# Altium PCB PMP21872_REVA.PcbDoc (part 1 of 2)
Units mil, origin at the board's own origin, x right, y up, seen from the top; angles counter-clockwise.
Board outline 2225 x 1350 mil, 4 copper layers (Top Layer, Signal Layer 1, Signal Layer 2, Bottom Layer), stack 61.6 mil thick; 75 components, 39 nets, 233 pads, 165 vias.
Unrouted connection lines stored in the file: 51.
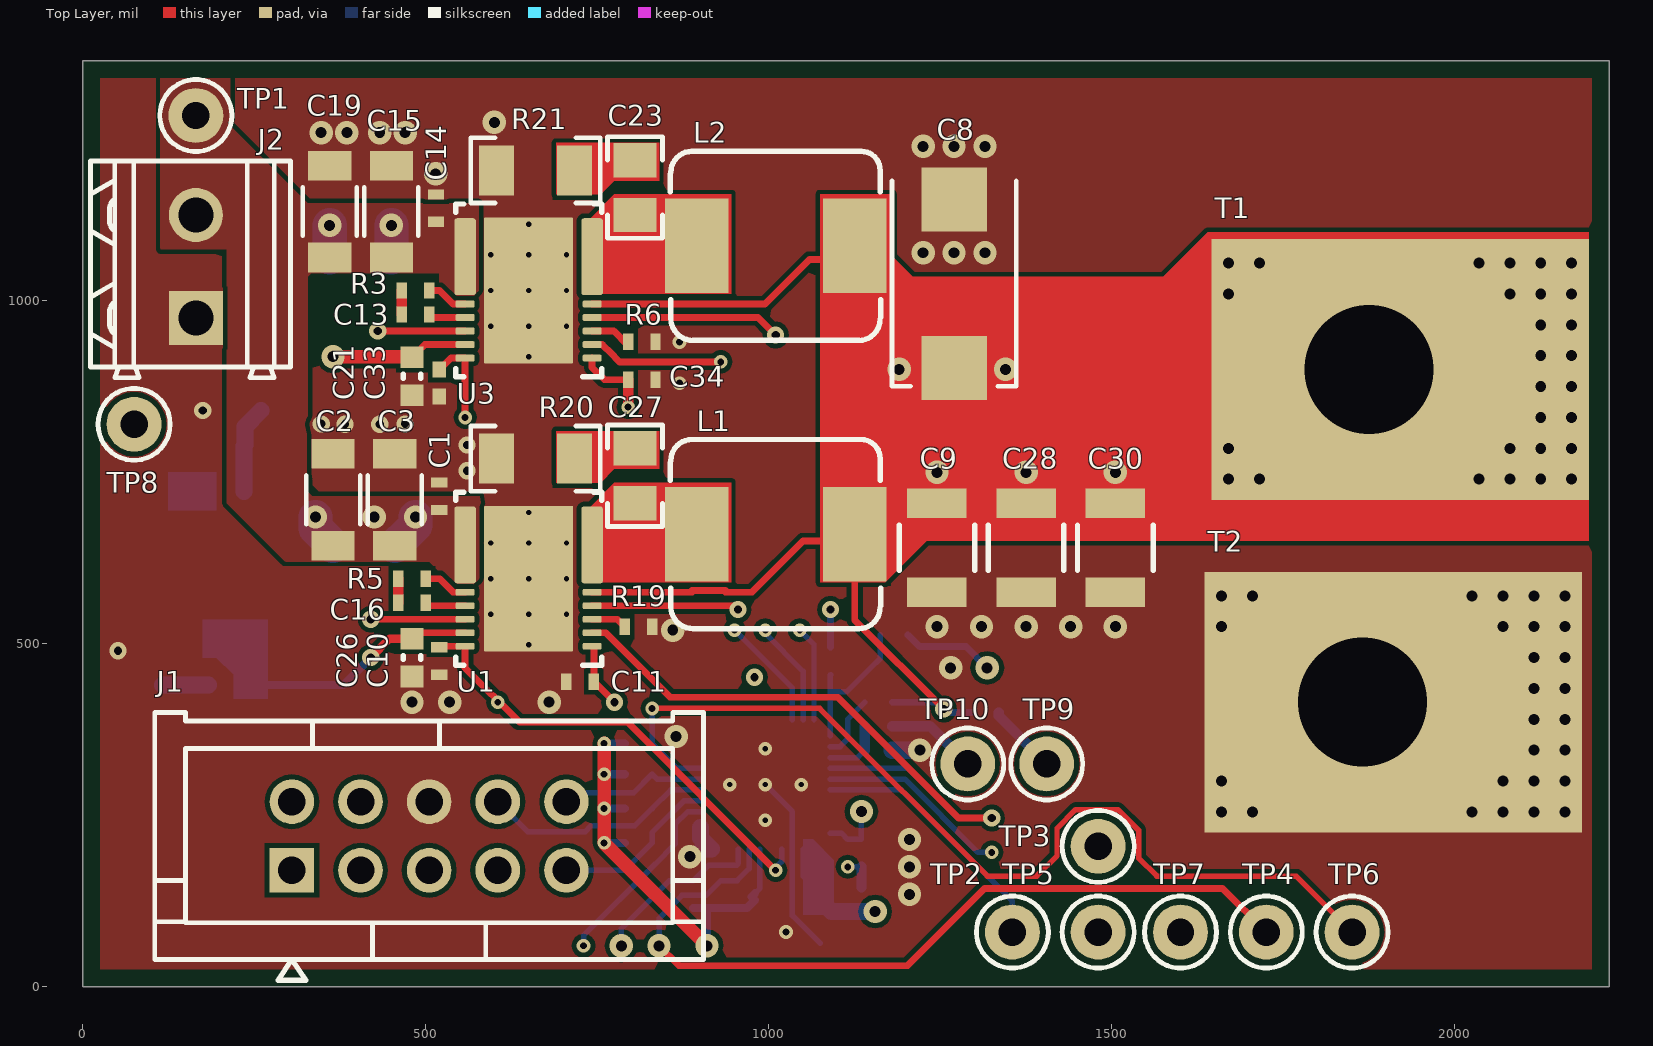
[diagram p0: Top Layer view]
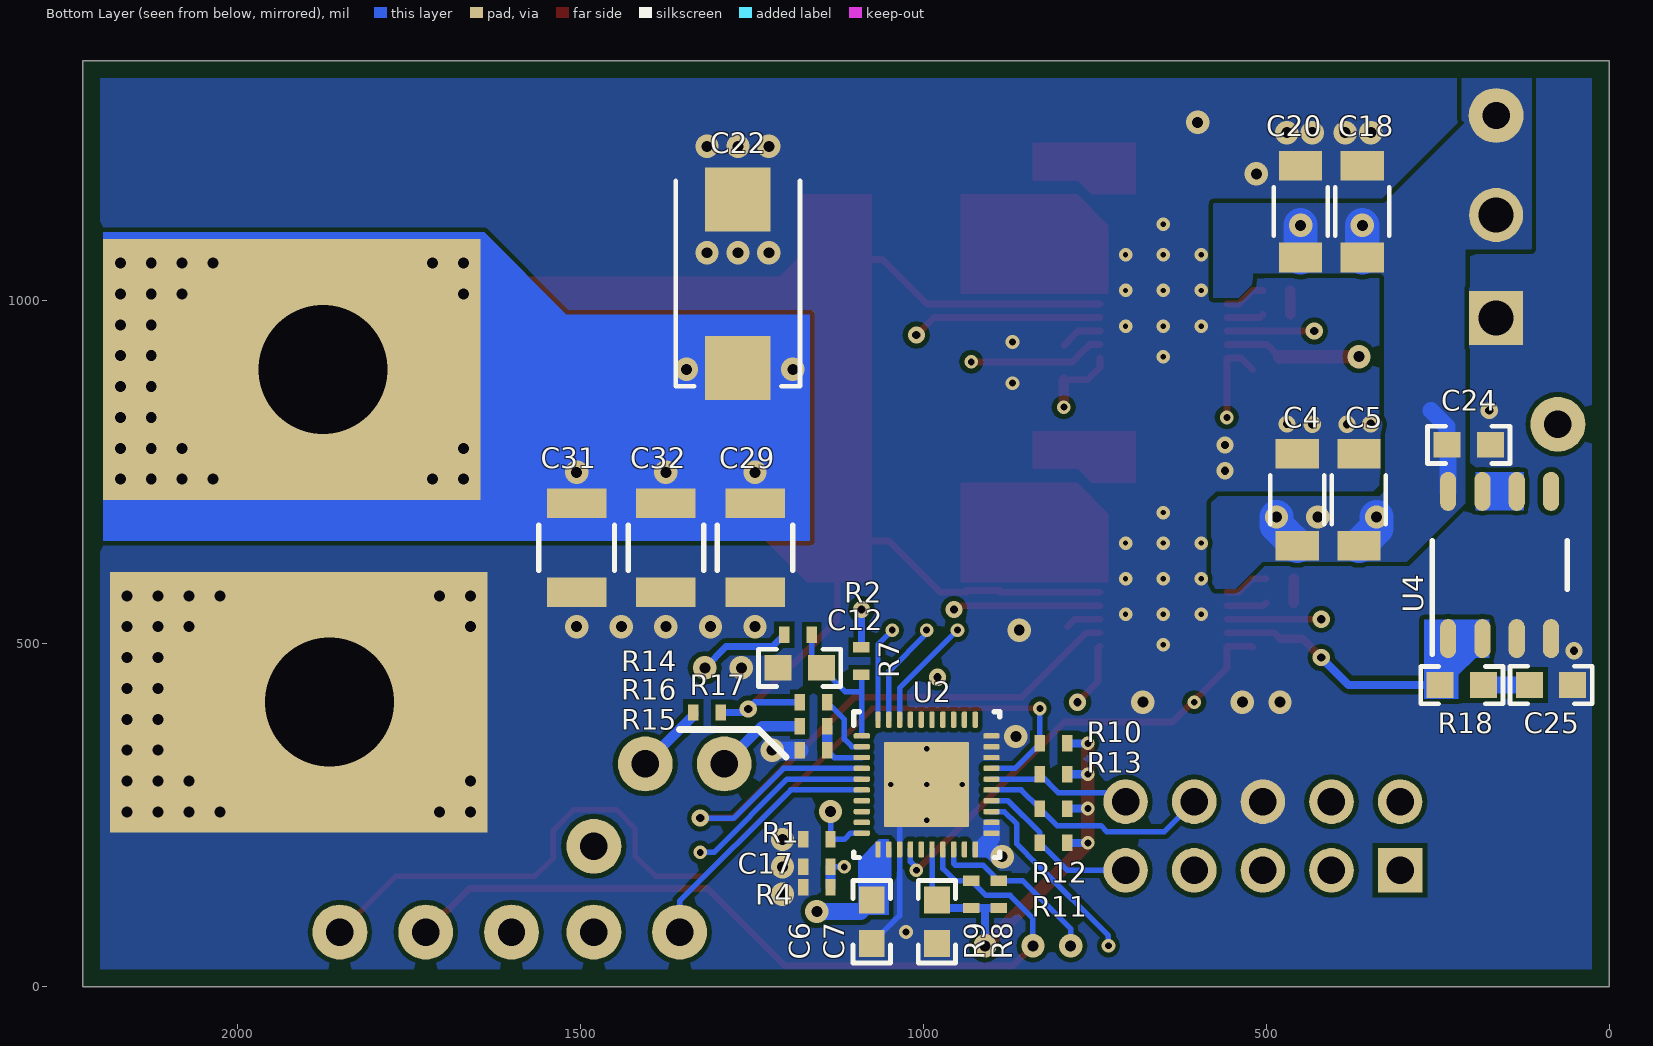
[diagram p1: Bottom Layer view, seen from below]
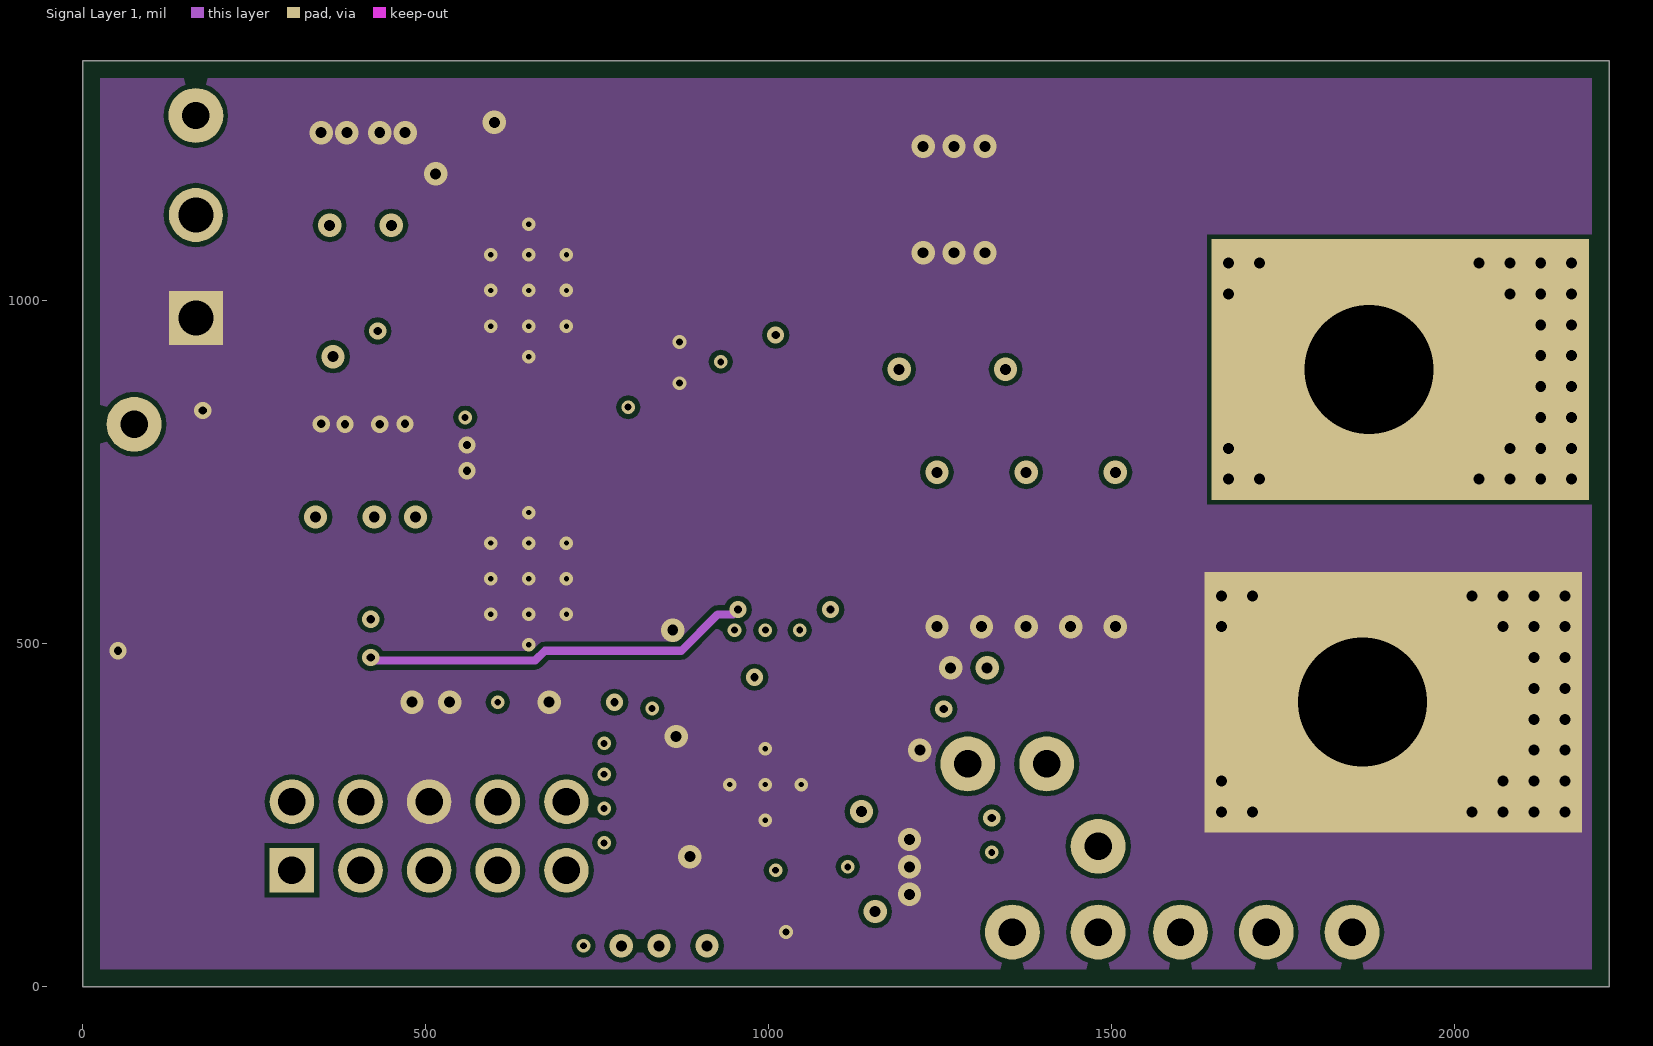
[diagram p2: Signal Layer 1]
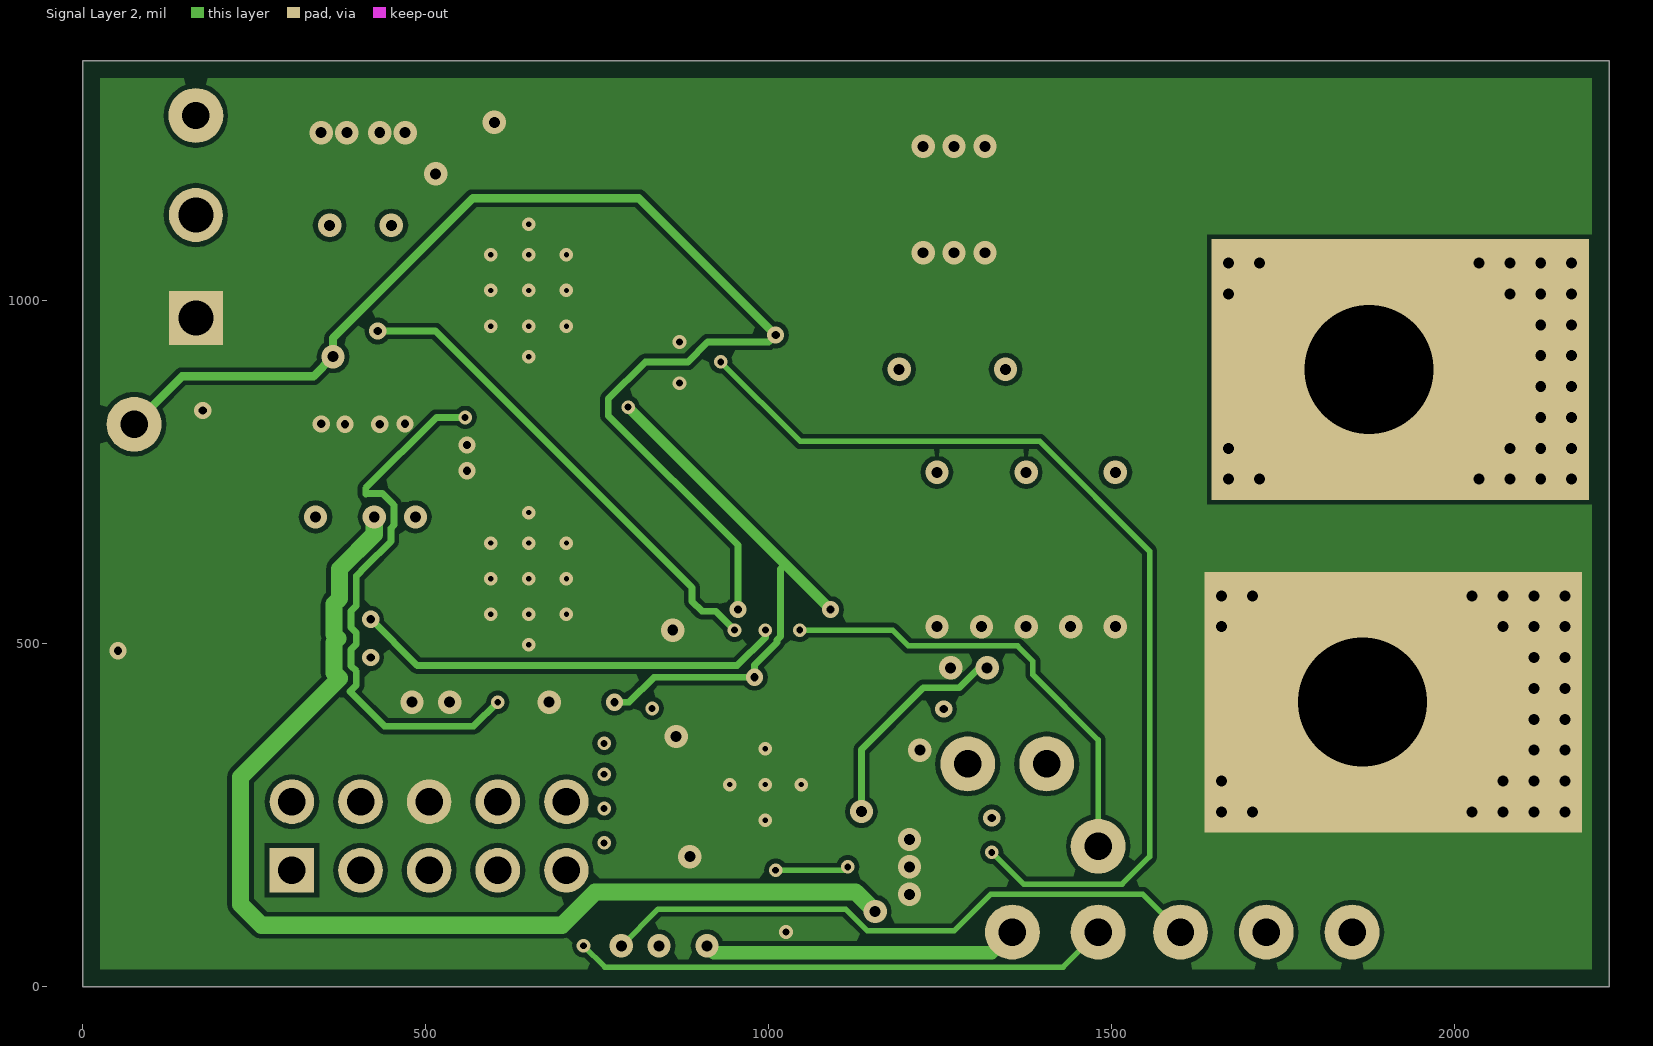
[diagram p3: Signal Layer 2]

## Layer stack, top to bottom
Top Solder: solder mask 0.4, Solder Resist, Dk 3.5
Top Layer: signal copper 1.4
Dielectric 1: prepreg 8, FR-4, Dk 4.2
Signal Layer 1: signal copper 1.4
Dielectric 2: core 40, FR-4, Dk 4.2
Signal Layer 2: signal copper 1.4
Dielectric 3: prepreg 8, FR-4, Dk 4.2
Bottom Layer: signal copper 1.4
Bottom Solder: solder mask 0.4, Solder Resist, Dk 3.5

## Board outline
0,0 2225,0 2225,1350 0,1350

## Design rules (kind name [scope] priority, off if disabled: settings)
AcuteAngle [All] p1: minimum=4.50000000000000E+0001 checktracksonly=FALSE
AssemblyTestPointUsage [All] p1: valid=2
BoardOutlineClearance BoardOutlineClearance_MountingHoles [OnCopper and InComponentClass('Mounting Holes')] p1: gap=25 ignorepadtopadclearanceinfootprint=FALSE
BoardOutlineClearance BoardOutlineClearance_Poly [OnCopper and InPoly] p2: gap=25 ignorepadtopadclearanceinfootprint=FALSE
BoardOutlineClearance [OnCopper and Not InComponentClass('Logo') and not InComponentClass('FiducialMark') and not InRegion(1000,500,4000,800)] p3: gap=25 ignorepadtopadclearanceinfootprint=FALSE
Clearance "Stitching to Stitching" [IsStitchingVia vs IsStitchingVia] p1: gap=7 ignorepadtopadclearanceinfootprint=FALSE
Clearance Clearance_Fiducial [InComponent('FID1') Or InComponent('FID2') Or InComponent('FID3')] p2: gap=0 ignorepadtopadclearanceinfootprint=FALSE
Clearance Clearance_Keepouts [((IsTrack Or IsArc) And Not InPoly) And IsFree and IsKeepOut vs ((IsTrack Or IsArc) And Not InPoly) And IsFree and IsKeepOut] p3: gap=0 ignorepadtopadclearanceinfootprint=FALSE
Clearance [All] p4: gap=7 ignorepadtopadclearanceinfootprint=FALSE
Clearance Clearance_Poly [InPolygon] p5: gap=4 ignorepadtopadclearanceinfootprint=FALSE
ComponentClearance ComponentClearance_BGA [HasParameterValue('CompType', 'IC')] p1: gap=4 collisioncheckmode=3 verticalgap=10 showdistances=TRUE
ComponentClearance ComponentClearance_Cap-Resistor [HasParameterValue('CompType', 'Resistor') Or HasParameterValue('CompType', 'Capacitor') Or HasParameterValue('CompType', 'Inductor')] p2: gap=4 collisioncheckmode=3 verticalgap=0 showdistances=TRUE
ComponentClearance ComponentClearance_MountingHoles_FiducialMarks [InComponentClass('Mounting Holes') vs InComponentClass('FiducialMark')] p3: gap=50 collisioncheckmode=3 verticalgap=10 showdistances=FALSE
ComponentClearance ComponentClearance_Shunt [InComponentClass('Header') vs InComponentClass('Shunt')] p4: gap=0 collisioncheckmode=3 verticalgap=0 showdistances=FALSE
ComponentClearance ComponentClearance_Logo [InComponentClass('Logo')] p5: gap=50 collisioncheckmode=3 verticalgap=10 showdistances=FALSE
ComponentClearance ComponentClearance_ScrewToNut [(HasFootprint('NY PMS 440 0025 PH')) vs (HasFootprint('Keystone_1902C'))] p6: gap=5 collisioncheckmode=3 verticalgap=10 showdistances=FALSE
ComponentClearance ComponentClearance_MountingHoles [InComponentClass('Mounting Holes')] p7: gap=250 collisioncheckmode=3 verticalgap=100000 showdistances=FALSE
ComponentClearance ComponentClearance_SmallPassives [HasFootprint('0201*') or HasFootprint('0402*') or HasFootprint('0508') or HasFootprint('0603*') or HasFootprint('0612') or HasFootprint('0805*') or HasFootprint('0815*') or HasFootprint('0830*') or HasFootprint('1206*') or HasFootprint('1210*') or HasFootprint('1808*') or HasFootprint('1812*') or HasFootprint('1825*') or HasFootprint('2010*') or HasFootprint('2220*') or HasFootprint('2225*') or HasFootprint('2512*') or HasFootprint('2728*') or HasFootprint('3518*') vs HasFootprint('0201*') or HasFootprint('0402*') or HasFootprint('0508') or HasFootprint('0603*') or HasFootprint('0612') or HasFootprint('0805*') or HasFootprint('0815*') or HasFootprint('0830*') or HasFootprint('1206*') or HasFootprint('1210*') or HasFootprint('1808*') or HasFootprint('1812*') or HasFootprint('1825*') or HasFootprint('2010*') or HasFootprint('2220*') or HasFootprint('2225*') or HasFootprint('2512*') or HasFootprint('2728*') or HasFootprint('3518*')] p8: gap=2 collisioncheckmode=3 verticalgap=10 showdistances=FALSE
ComponentClearance ComponentClearance_THtoSMT [IsThruComponent vs IsSMTComponent] p9: gap=15 collisioncheckmode=3 verticalgap=30 showdistances=FALSE
ComponentClearance ComponentClearance_THtoTH [IsThruComponent vs IsThruComponent] p10: gap=15 collisioncheckmode=3 verticalgap=30 showdistances=FALSE
ComponentClearance [All] p11: gap=2 collisioncheckmode=3 verticalgap=10 showdistances=FALSE
DiffPairsRouting [All] p1: maxlimit=100 minlimit=10 mostfreqgap=10 toplayer_minwidth=15 toplayer_maxwidth=15 toplayer_prefwidth=15 midlayer1_minwidth=15 midlayer1_maxwidth=15 midlayer1_prefwidth=15 midlayer2_minwidth=15 midlayer2_maxwidth=15 midlayer2_prefwidth=15 bottomlayer_minwidth=15 bottomlayer_maxwidth=15 bottomlayer_prefwidth=15 maxuncoupledlength=1000
FabricationTestPointUsage TestPointUsage [All] p1: valid=2 allowmultiple=FALSE
FabricationTestpoint Testpoint [All] p1: side=3 testpointundercomponent=TRUE minsize=40 maxsize=100 preferedsize=60 minholesize=0 maxholesize=40 preferedholesize=32 testpointgrid=1 allowsidetop=TRUE allowsidebottom=TRUE usegrid=TRUE gridtolerance=0.01
FanoutControl Fanout_LCC [IsLCC] p1: bgadir=Out bgaviamode=Centered fanoutstyle=Auto fanoutdirection=Alternating viagrid=1 // Fanout_LCC (Default Rule)
FanoutControl Fanout_BGA [IsBGA] p2: bgadir=Out bgaviamode=Centered fanoutstyle=Auto fanoutdirection=Alternating viagrid=1 // Fanout_BGA (Default Rule)
FanoutControl Fanout_Default [All] p4: bgadir=Out bgaviamode=Centered fanoutstyle=Auto fanoutdirection=Alternating viagrid=1 // Fanout_Default (Default Rule)
FanoutControl Fanout_Small [(CompPinCount < 5)] p5: bgadir=Out bgaviamode=Centered fanoutstyle=Auto fanoutdirection=OutThenIn viagrid=1 // Fanout_Small (Default Rule)
HoleSize [All] p1: absolutevalues=TRUE maxlimit=251 minlimit=5 maxpercent=80.000 minpercent=20.000
HoleToHoleClearance [All] p1: gap=6 allowstackedmicrovias=TRUE
MinimumAnnularRing MinimumAnnularRing_ThermalPadVias [IsVia and InAnyComponent] p1: minimumring=5.91
MinimumAnnularRing [All] p2: minimumring=1.5
MinimumSolderMaskSliver MinimumSolderMaskSliver_Logo [InComponentClass('Logo') vs InComponentClass('Logo')] p1: minsoldermaskwidth=0.7
MinimumSolderMaskSliver [All] p2: minsoldermaskwidth=1.5
PlaneClearance PlaneClearance_GND [InNet('GND')] p1: clearance=6
PlaneClearance PlaneClearance_GND_1 [InNet('GND') And InPolygon] p2: clearance=6
PlaneClearance [All] p3: clearance=15
PlaneConnect [All] p1: planeconnectstyle=Direct reliefexpansion=10 reliefentries=4 reliefconductorwidth=10 reliefairgap=10
PolygonConnect [All] p1: connectstyle=Direct reliefconductorwidth=10 reliefentries=4 polygonreliefangle="90 Angle" airgapwidth=10
RoutingVias RoutingVias_Connectors [HasCompParameterValue('PartNumber','CB35-36-CY')] p1: holewidth=12 width=32 viastyle="Through Hole" minholewidth=0 minwidth=0 maxholewidth=1000 maxwidth=1000
RoutingVias ThermalPadVias [IsVia and InAnyComponent] p2: holewidth=6 width=10 viastyle="Through Hole" minholewidth=7.87 minwidth=19.68 maxholewidth=12.99 maxwidth=23.62
RoutingVias [All] p3: holewidth=6 width=10 viastyle="Through Hole" minholewidth=6 minwidth=10 maxholewidth=40 maxwidth=65
SilkToBoardRegionClearance [Not ((IsComment or IsDesignator) And (Hide <> 'False')) and not InRegion(1000,500,4000,800)] p1:
SilkToSilkClearance SilkToSilkClearance_Pb-FreeLogo [(HasFootprint('Pb-Free_Overlay_Medium') OR HasFootprint('Pb-Free_Overlay_Small')) vs (HasFootprint('Pb-Free_Overlay_Medium') OR HasFootprint('Pb-Free_Overlay_Small'))] p1: silktosilkclearance=0
SilkToSilkClearance [All] p2: silktosilkclearance=0
SilkToSolderMaskClearance SilkToComponentPadClearance [IsPad and InAnycomponent] p1: minsilkscreentomaskgap=0 clearancetoexposedcopper=TRUE
SilkToSolderMaskClearance "Silk to Solder Mask Opening" [All] p2: minsilkscreentomaskgap=0 clearancetoexposedcopper=FALSE
SolderMaskExpansion [All] p1: expansion=1.97
Width [All] p1: maxlimit=100 minlimit=4 preferedwidth=12 checkconnectedcopper=TRUE
13 further rules are at their usual default settings.

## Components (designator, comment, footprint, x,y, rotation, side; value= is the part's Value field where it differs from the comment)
C1 "GRM155R71E222KA01D" 0402S 520,715.08 r90 top value=2200pF
C2 "GRM31CR61C226KE15L" 1206_180 365,710 r90 top value=22uF
C3 "GRM31CR61C226KE15L" 1206_180 455,710 r90 top value=22uF
C4 "GRM31CR61C226KE15L" 1206_180 455,710 r90 bottom value=22uF
C5 "GRM31CR61C226KE15L" 1206_180 365,710 r90 bottom value=22uF
C6 "CGJ3E1X7R1E105K080AC" 0603 1075,95 r270 bottom value=1uF
C7 "CGJ3E1X7R1E105K080AC" 0603 980,95 r270 bottom value=1uF
C8 "Cap_Polarized" 7343-20 1270,1025 r90 top value=470uF
C9 "Capacitor" 1210_280 1245,640 r270 top value=100uF
C10 "C0402C102J3GACTU" 0402S 520,475 r270 top value=1000pF
C11 "Capacitor" 0402S 725,445 r180 top value=0.1uF
C12 "CGJ3E1X7R1E105K080AC" 0603 1180,465 r0 bottom value=1uF
C13 "Capacitor" 0402S 485,980 r180 top value=0.1uF
C14 "GRM155R71E222KA01D" 0402S 515,1135 r90 top value=2200pF
C15 "GRM31CR61C226KE15L" 1206_180 450,1130 r90 top value=22uF
C16 "Capacitor" 0402S 480,560 r180 top value=0.1uF
C17 "GRM155R71C224KA12D" 0402S 1155,175 r0 bottom value=0.22uF
C18 "GRM31CR61C226KE15L" 1206_180 360,1130 r90 bottom value=22uF
C19 "GRM31CR61C226KE15L" 1206_180 360,1130 r90 top value=22uF
C20 "GRM31CR61C226KE15L" 1206_180 450,1130 r90 bottom value=22uF
C21 "Capacitor" 0603L 480,890 r270 top value=10uF
C22 "Cap_Polarized" 7343-20 1270,1025 r90 bottom value=470uF
C23 "Capacitor" 0805_HV 805,1165 r90 top value=1500pF
C24 "C1608X7R1E474K080AE" 0603 205,790 r180 bottom value=0.47uF
C25 "C1608X7R1E474K080AE" 0603 85,440 r180 bottom value=0.47uF
C26 "Capacitor" 0603L 480,480 r270 top value=10uF
C27 "Capacitor" 0805_HV 805,745 r90 top value=1500pF
C28 "Capacitor" 1210_280 1375,640 r270 top value=100uF
C29 "Capacitor" 1210_280 1245,640 r270 bottom value=100uF
C30 "Capacitor" 1210_280 1505,640 r270 top value=100uF
C31 "Capacitor" 1210_280 1505,640 r270 bottom value=100uF
C32 "Capacitor" 1210_280 1375,640 r270 bottom value=100uF
C33 "C1005C0G1E102J" 0402 520,880 r270 top value=1000pF
C34 "Capacitor" 0402S 815,885 r0 top value=0.1uF
J1 "5103308-1" CONN_5103308-1 505,220 r0 top
J2 "691214000000" Wurth_691214310002 165,1050 r90 top
L1 "CMLE064T-R22MS0R987" CMLE064T_-24 1010,660 r0 top value=220nH
L2 "CMLE064T-R22MS0R987" CMLE064T_-24 1010,1080 r0 top value=220nH
R1 "RC0402FR-07115KL" 0402S 1155,215 r180 bottom value=115k
R2 "CRCW0402162KFKED" 0402S 1182.56,513.06 r0 bottom value=162k
R3 "Resistor" 0402S 485,1015 r0 top value=2.2
R4 "CRCW0402121KFKED" 0402S 1155,145 r180 bottom value=121k
R5 "Resistor" 0402S 480,595 r0 top value=2.2
R6 "CRCW0402169KFKED" 0402S 815,940 r180 top value=169k
R7 "Resistor" 0402S 1090,475 r90 bottom value=0
R8 "ERJ-2GEJ103X" 0402S 890,135 r270 bottom value=10k
R9 "ERJ-2GEJ103X" 0402S 930,135 r270 bottom value=10k
R10 "ERJ-2GEJ103X" 0402S 810,355 r180 bottom value=10k
R11 "ERJ-2GEJ103X" 0402S 810,210 r180 bottom value=10k
R12 "ERJ-2GEJ103X" 0402S 810,260 r180 bottom value=10k
R13 "ERJ-2GEJ103X" 0402S 810,310 r180 bottom value=10k
R14 "ERJ-2GEJ101X" 0402S 1160,415 r180 bottom value=100
R15 "ERJ-2GEJ101X" 0402S 1160,345 r180 bottom value=100
R16 "Resistor" 0402S 1160,380 r0 bottom value=0
R17 "Resistor" 0402S 1315,400 r0 bottom value=0
R18 "ERJ-3RQFR33V" 0603 215,440 r0 bottom value=0.33
R19 "CRCW0402169KFKED" 0402S 810,525 r180 top value=169k
R20 "Resistor" 1206 660,770 r180 top value=1.0
R21 "Resistor" 1206 660,1190 r180 top value=1.0
T1 "CB35-36-CY" CB35-36-CY 1875,900 r180 top
T2 "CB35-36-CY" CB35-36-CY 1865,415 r180 top
TP1 "5000" Keystone5000 165,1270 r90 top
TP2 "5000" Keystone5000 1355,80 r90 top
TP3 "5003" Keystone5003 1480,205 r0 top
TP4 "5003" Keystone5003 1725,80 r0 top
TP5 "5003" Keystone5003 1480,80 r0 top
TP6 "5003" Keystone5003 1850,80 r0 top
TP7 "5003" Keystone5003 1600,80 r0 top
TP8 "5000" Keystone5000 75,820 r90 top
TP9 "5000" Keystone5000 1405,325 r90 top
TP10 "5003" Keystone5003 1290,325 r0 top
U1 "CSD95490Q5MC" DMC0012A 650,595 r180 top
U2 "TPS53622RSBR" RSB0040E 995,295 r180 bottom
U3 "CSD95490Q5MC" DMC0012A 650,1015 r180 top
U4 "TI-LP2951-50D8" D0008A_N 160,615 r90 bottom

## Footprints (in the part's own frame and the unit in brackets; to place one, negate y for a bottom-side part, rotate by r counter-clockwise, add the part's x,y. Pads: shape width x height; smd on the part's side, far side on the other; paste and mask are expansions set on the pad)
0402 [mm] "Chip Capacitor, Body 1.0x0.5mm, IPC High Density"
  rect 0.6x0.5 smd: 1(-0.5,0) 2(0.5,0)
  body extent -0.55,-0.3 0.55,0.3, height 1.3
0402S [mil] "Based on C0402S footprint from PADS legacy"
  rect 15x24 smd: 1(-20,0) 2(20,0)
  body extent -22,-12 22,12, height 24
0603 [mm] "0603 from SM-752 data"
  rect 1x0.95 smd: 1(-0.8,0) 2(0.8,0)
  silkscreen extent -1.52,-0.69 1.52,0.69, body extent -0.87,-0.47 0.87,0.47, height 1
0603L [mm] "0603 from SM-752 data"
  rect 0.8x0.85 smd: 1(-0.7,0) 2(0.7,0)
  silkscreen extent -0.07,-0.33 0.07,0.33, body extent -0.87,-0.47 0.87,0.47, height 1
0805_HV [mil] "0805 with 30mil clearance between pads"
  rect 50x63 smd: 1(-40,0) 2(40,0)
  silkscreen extent -74,-40 74,40, body extent -43,-29 43,29, height 57
1206 [mm] "1206 from SM-752 data"
  rect 1.3x1.85 smd: 1(-1.45,0) 2(1.45,0)
  silkscreen extent -2.4,-1.21 2.4,1.21, body extent -1.7,-0.9 1.7,0.9, height 1.35
1206_180 [mm] "1206_180"
  rect 1.1x1.6 smd: 1(-1.7,0) 2(1.7,0)
  silkscreen extent -0.9,-1 0.9,1, body extent -1.75,-0.95 1.75,0.95, height 1.8
1210_280 [mm] "SMD, 2-Leads, Body 3.6x2.8mm, Height 2.8mm"
  rect 1.1x2.2 smd: 1(-1.65,0) 2(1.65,0)
  silkscreen extent -0.84,-1.4 0.84,1.4, body extent -1.8,-1.4 1.8,1.4, height 2.8
7343-20 [mm] "Medium density IPC, based on Kemet case V from T495 datasheet"
  rect 2.37x2.43 smd: 1(-3.12,0) 2(3.12,0)
  silkscreen extent -3.8,-2.3 3.8,2.3, body extent -3.8,-2.3 3.8,2.3, height 2
CB35-36-CY [mil] "Terminal 50A Lug"
  rect 550x380 hole 188 copper offset -45,0 paste-190: 1(0,0)
  body extent -960,-189 230,191, height 614
CMLE064T_-24 [mm] "CYNTEC"
  rect 2.35x3.5 smd: 1(-2.925,0) 2(2.925,0)
  silkscreen extent -3.9,-3.5 3.88,3.5, body extent -3.8,-3.4 3.8,3.4, height 4
CONN_5103308-1 [mm] "TE Connectivity (AMP) Rev E datasheet"
  rect 1.65x1.65 hole 1.016 mask+0: 1(-5.08,-1.27)
  round 1.65 hole 1.016 mask+0: 2(-5.08,1.27) 3(-2.54,-1.27) 4(-2.54,1.27) 5(0,-1.27) 6(0,1.27) 7(2.54,-1.27) 8(2.54,1.27) 9(5.08,-1.27) 10(5.08,1.27)
  silkscreen extent -10.16,-5.33 10.16,4.57, body extent -10.16,-4.57 10.16,4.57, height 9.87
D0008A_N [mm] "SOIC, 8-Leads, Body 4.9x3.9mm, Pitch 1.27mm, IPC Medium Density"
  oval 1.45x0.6 smd: 1(-2.725,1.905) 2(-2.725,0.635) 3(-2.725,-0.635) 4(-2.725,-1.905) 5(2.725,-1.905) 6(2.725,-0.635) 7(2.725,0.635) 8(2.725,1.905)
  silkscreen extent -3.3,-2.5 0.9,2.5, body extent -3,-2.45 3,2.45, height 1.63
DMC0012A [mm] "exported from UL then modified"
  rrect40% 0.7x0.25 smd: 1(-2.35,2.501) 2(-2.35,2.001) 3(-2.35,1.5) 4(-2.35,1) 5(-2.35,0.5) 8(2.35,0.5) 9(2.35,1) 10(2.35,1.5) 11(2.35,2.001) 12(2.35,2.501)
  rrect25% 0.8x2.85 smd paste-0.4 mask-0.4: 6(-2.35,-1.25) 7(2.35,-1.25)
  rrect9% 1.41x1.12 on Top Paste: 13(-0.805,1.98) 13(-0.805,0.66) 13(-0.805,-0.66) 13(-0.805,-1.98) 13(0.805,1.98) 13(0.805,0.66) 13(0.805,-0.66) 13(0.805,-1.98)
  rrect3% 3.3x5.4 smd paste-1.7: 13(0,0)
  silkscreen extent -2.7,-3.2 2.7,3.2, body extent -2.5,-3 2.5,3, height 1.05
Keystone5000 [mil] "For Keystone 500x miniature loop terminals"
  round 80 hole 40: 1(0,0)
  silkscreen extent -52,-52 52,52, body extent -49,-49 49,49, height 182
Keystone5003 [mil] "For Keystone 500x miniature loop terminals"
  round 80 hole 40: 1(0,0)
  silkscreen extent -52,-52 52,52, body extent -49,-49 49,49, height 182
RSB0040E [mm] "QFN, 40-Leads, Body 5x5mm, Pitch 0.4mm, Thermal Pad 3.15x3.15mm, TI Recommended"
  rrect50% 0.6x0.2 smd: 1(-2.4,1.8) 2(-2.4,1.4) 3(-2.4,1) 4(-2.4,0.6) 5(-2.4,0.2) 6(-2.4,-0.2) 7(-2.4,-0.6) 8(-2.4,-1) 9(-2.4,-1.4) 10(-2.4,-1.8) 21(2.4,-1.8) 22(2.4,-1.4) 23(2.4,-1) 24(2.4,-0.6) 25(2.4,-0.2) 26(2.4,0.2) 27(2.4,0.6) 28(2.4,1) 29(2.4,1.4) 30(2.4,1.8)
  rrect50% 0.2x0.6 smd: 11(-1.8,-2.4) 12(-1.4,-2.4) 13(-1,-2.4) 14(-0.6,-2.4) 15(-0.2,-2.4) 16(0.2,-2.4) 17(0.6,-2.4) 18(1,-2.4) 19(1.4,-2.4) 20(1.8,-2.4) 31(1.8,2.4) 32(1.4,2.4) 33(1,2.4) 34(0.6,2.4) 35(0.2,2.4) 36(-0.2,2.4) 37(-0.6,2.4) 38(-1,2.4) 39(-1.4,2.4) 40(-1.8,2.4)
  rrect7% 1.37x1.37 on Bottom Paste: 41(-0.785,-0.785) 41(-0.785,0.785) 41(0.785,-0.785) 41(0.785,0.785)
  rrect3% 3.15x3.15 smd paste-1.575: 41(0,0)
  silkscreen extent -2.7,-2.7 2.7,2.7, body extent -2.55,-2.55 2.55,2.55, height 0.81
Wurth_691214310002 [mm] "WE"
  rect 2x2 hole 1.3: 1(-1.905,0)
  round 2 hole 1.3: 2(1.905,0)
  silkscreen extent -4.12,-3.5 3.9,3.9, body extent -4.12,-3.5 3.9,3.9, height 8.52

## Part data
C1 C14: library part CMP-0006663-2, "CAP, CERM, 2200 pF, 25 V, +/- 10%, X7R, 0402", Cap_Case=0402, Manufacturer=MuRata, Supplier Part Number 1=490-5419-1-ND, TempCo=X7R, Tolerance_%=10%, Value1=Unknown, Value2=25V, ValueDisplayed=2200pF
C2 C3 C4 C5 C15 C18 C19 C20: library part CMP-0008946-2, "CAP, CERM, 22 uF, 16 V, +/- 10%, X5R, 1206", Cap_Case=1206, Manufacturer=MuRata, Supplier Part Number 1=GRM31CR61C226KE15L-ND, TempCo=X5R, Tolerance_%=10%, Value1=Unknown, Value2=16V, ValueDisplayed=22uF
C6 C7 C12: library part CMP-0083856-1, "CAP, CERM, 1 µF, 25 V,+/- 10%, X7R, 0603", Cap_Case=0603, Manufacturer=TDK, TempCo=X7R, Tolerance_%=10%, Value2=25V, ValueDisplayed=1µF
C8 C22: library part CMP-0012257-4, "CAP, Aluminum Polymer, 470 uF, 2.5 V, +/- 20%, 4.5 ohm, 7343-20, SMD", Cap_Case=7343-20, Manufacturer=Panasonic, PartNumber=EEFSX0E471E4, Supplier Part Number 1=PCE5042CT-ND, Tolerance_%=20%, Value1="4.5 ohm", Value2=2.5V, ValueDisplayed=470uF
C9 C28 C29 C30 C31 C32: library part CMP-0009083-2, "CAP, CERM, 100 uF, 6.3 V, +/- 20%, X5R, 1210", Cap_Case=1210, Manufacturer=Kemet, PartNumber=C1210C107M9PACTU, Supplier Part Number 1=399-4697-1-ND, TempCo=X5R, Tolerance_%=20%, Value1=Unknown, Value2=6.3V, ValueDisplayed=100uF
C10: library part CMP-0081059-1, "CAP, CERM, 1000 pF, 25 V,+/- 5%, C0G/NP0, 0402", Cap_Case=0402, Manufacturer=Kemet, Supplier Part Number 1=399-7751-1-ND, TempCo=C0G/NP0, Tolerance_%=5%, Value2=25V, ValueDisplayed=1000pF
C11 C34: library part CMP-0006591-2, "CAP, CERM, 0.1 uF, 16 V, +/- 10%, X5R, 0402", Cap_Case=0402, Manufacturer=MuRata, PartNumber=GRM155R61C104KA88D, Supplier Part Number 1=490-5415-1-ND, TempCo=X5R, Tolerance_%=10%, Value1=Unknown, Value2=16V, ValueDisplayed=0.1uF
C13 C16: library part CMP-0006607-2, "CAP, CERM, 0.1 uF, 25 V, +/- 10%, X5R, 0402", Cap_Case=0402, Manufacturer=MuRata, PartNumber=GRM155R61E104KA87D, Supplier Part Number 1=490-5920-1-ND, TempCo=X5R, Tolerance_%=10%, Value1=Unknown, Value2=25V, ValueDisplayed=0.1uF
C17: library part CMP-0006648-2, "CAP, CERM, 0.22 uF, 16 V, +/- 10%, X7R, 0402", Cap_Case=0402, Manufacturer=MuRata, Supplier Part Number 1=490-5418-1-ND, TempCo=X7R, Tolerance_%=10%, Value1=Unknown, Value2=16V, ValueDisplayed=0.22uF
C21 C26: library part CMP-0006872-5, "CAP, CERM, 10 uF, 6.3 V, +/- 20%, X5R, 0603", Cap_Case=0603, Manufacturer=Kemet, PartNumber=C0603C106M9PACTU, Supplier Part Number 1=399-5504-1-ND, TempCo=X5R, Tolerance_%=20%, Value1="0.004 ohm", Value2=6.3V, ValueDisplayed=10uF
C23 C27: library part CMP-0007545-2, "CAP, CERM, 1500 pF, 100 V, +/- 10%, X7R, 0805", Cap_Case=0805, Manufacturer=AVX, PartNumber=08051C152KAT2A, Supplier Part Number 1=478-1353-1-ND, TempCo=X7R, Tolerance_%=10%, Value1="0.229 ohm", Value2=100V, ValueDisplayed=1500pF
C24 C25: library part CMP-0750175-1, "CAP, CERM, 0.47 µF, 25 V,+/- 10%, X7R, 0603", Cap_Case=0603, Manufacturer=TDK, TempCo=X7R, Tolerance_%=10%, Value2=25V, ValueDisplayed=0.47µF
C33: "CAP, CERM, 1000 pF, 25 V, +/- 5%, C0G/NP0, 0402", Cap_Case=0402, Manufacturer=TDK, Supplier Part Number 1=445-2651-1-ND, TempCo=C0G/NP0, Tolerance_%=5, Value1=Unknown, Value2=25V, ValueDisplayed=1000pF
J1: library part CMP-0054834-2, "Header (shrouded), 100mil, 5x2, Gold, TH", Manufacturer="TE Connectivity", Supplier Part Number 1=A33159-ND
J2: library part CMP-0054822-1, "Terminal Block, 2x1, 3.81mm, 24-16 AWG, 10A, 300VAC, TH", Manufacturer="Wurth Elektronik"
L1 L2: library part CMP-0059637-1, "Inductor, 220 nH, 28.5 A, 0.00098 ohm, SMD", Manufacturer=Cyntec, Value1="0.00098 ohm", Value2=28.5A, ValueDisplayed=220nH
R1: library part CMP-0077551-1, "RES, 115 k, 1%, 0.063 W, 0402", Manufacturer="Yageo America", Power_W=63mW, Supplier Part Number 1=YAG2956CT-ND, TempCo="100 ppm/C", Tolerance_%=1%, Value2=0.063W, Value_Code=115k
R2: library part CMP-0026034-3, "RES, 162 k, 1%, 0.063 W, AEC-Q200 Grade 0, 0402", Manufacturer=Vishay-Dale, Power_W=63mW, Supplier Part Number 1=541-162KLCT-ND, TempCo="100 ppm/C", Tolerance_%=1%, Value2=0.063W, Value_Code=162k
R3 R5: library part CMP-0026898-3, "RES, 2.2, 5%, 0.063 W, AEC-Q200 Grade 0, 0402", Manufacturer=Vishay-Dale, PartNumber=CRCW04022R20JNED, Power_W=63mW, Supplier Part Number 1=541-2.2JCT-ND, TempCo="200 ppm/C", Tolerance_%=5%, Value2=0.063W, Value_Code=2R20, ValueDisplayed=2.2
R4: library part CMP-0025984-3, "RES, 121 k, 1%, 0.063 W, AEC-Q200 Grade 0, 0402", Manufacturer=Vishay-Dale, Power_W=63mW, Supplier Part Number 1=541-121KLCT-ND, TempCo="100 ppm/C", Tolerance_%=1%, Value2=0.063W, Value_Code=121k
R6 R19: library part CMP-0026038-3, "RES, 169 k, 1%, 0.063 W, AEC-Q200 Grade 0, 0402", Manufacturer=Vishay-Dale, Power_W=63mW, Supplier Part Number 1=541-169KLCT-ND, TempCo="100 ppm/C", Tolerance_%=1%, Value2=0.063W, Value_Code=169k
R7 R16 R17: library part CMP-0026822-3, "RES, 0, 5%, 0.063 W, AEC-Q200 Grade 0, 0402", Manufacturer=Vishay-Dale, PartNumber=CRCW04020000Z0ED, Power_W=63mW, Supplier Part Number 1=541-0.0JCT-ND, TempCo="200 ppm/C", Tolerance_%=5%, Value2=0.063W, Value_Code=0000, ValueDisplayed=0
R8 R9 R10 R11 R12 R13: library part CMP-0026994-4, "RES, 10 k, 5%, 0.1 W, AEC-Q200 Grade 0, 0402", Manufacturer=Panasonic, Power_W=100mW, Supplier Part Number 1=P10KJCT-ND, TempCo="200 ppm/C", Tolerance_%=5%, Value2=0.1W, Value_Code=10k0, ValueDisplayed=10k
R14 R15: library part CMP-0026993-2, "RES, 100, 5%, 0.1 W, AEC-Q200 Grade 0, 0402", Manufacturer=Panasonic, Power_W=100mW, Supplier Part Number 1=P100JCT-ND, TempCo="200 ppm/C", Tolerance_%=5%, Value2=0.1W, Value_Code=100R, ValueDisplayed=100
R18: library part CMP-0022714-1, "RES, 0.33, 1%, 0.1 W, 0603", Manufacturer=Panasonic, Power_W=100mW, Supplier Part Number 1=P.33AJCT-ND, TempCo="300 ppm/C", Tolerance_%=1%, Value2=0.1W, Value_Code=R330, ValueDisplayed=0.33
R20 R21: library part CMP-0018745-2, "RES, 1.0, 5%, 0.5 W, 1206", Manufacturer=Bourns, PartNumber=CRM1206-JW-1R0ELF, Power_W=500mW, Supplier Part Number 1=652-CRM1206JW1R0ELF, TempCo="150 ppm/C", Tolerance_%=5%, Value2=0.5W, Value_Code=1R00, ValueDisplayed=1.0
T1 T2: library part CMP-0055442-1, "Terminal 50A Lug", Manufacturer=Panduit, Supplier Part Number 1=CB35-36-CY-ND, Voltage_V=600V
TP1 TP2 TP8 TP9: library part CMP-0055137-1, "Test Point, Miniature, Red, TH", Color=Red, Manufacturer=Keystone, Supplier Part Number 1=36-5000-ND
TP3 TP4 TP5 TP6 TP7 TP10: library part CMP-0055140-1, "Test Point, Miniature, Orange, TH", Color=Orange, Manufacturer=Keystone, Supplier Part Number 1=36-5003-ND
U1 U3: library part CMP-0013339-3, "Synchronous Buck NexFET Power Stage, DMC0012A (VSON-CLIP-12)", Alternate Manufacturer="Texas Instruments", Alternate PartNumber=CSD95490Q5MCT
U2: library part CMP-0077545-2, "Dual-Channel (1-Phase + 1-Phase) or (2-Phase + 0-Phase) D-CAP+Step-Down Multiphase Controller with NVM and PMBus for VR13 Server V CCIO + V MCP, RSB0040E (WQFN-40)", Alternate Manufacturer="Texas Instruments", Alternate PartNumber=TPS53622RSBT
U4: library part CMP-0037104-1, "Fixed Regulator with 1 to 30 V Input and 1.2 to 30 V Output, -40 to 125 degC, 8-Pin SOIC (D), Green (RoHS & no Sb/Br)", Manufacturer="Texas Instruments", PartNumber=LP2951-50DR

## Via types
v1: diameter 32, hole 16, Top Layer to Bottom Layer, 56 vias
v2: diameter 34, hole 16, Top Layer to Bottom Layer, tented both sides, 45 vias
v3: diameter 19.68, hole 7.87, Top Layer to Bottom Layer, 27 vias
v4: diameter 20, hole 10, Top Layer to Bottom Layer, tented both sides, 19 vias
v5: diameter 25, hole 12, Top Layer to Bottom Layer, tented both sides, 18 vias

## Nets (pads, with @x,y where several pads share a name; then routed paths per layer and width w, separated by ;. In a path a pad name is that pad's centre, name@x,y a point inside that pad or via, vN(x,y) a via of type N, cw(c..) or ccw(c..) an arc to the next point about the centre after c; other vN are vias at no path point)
3v3vin: C7.1 R8.2 R9.2 R10.2 R11.2 R12.2 R13.2 TP2.1 U2.6 U2.16 | length 1540.2
  Top Layer w20: v4(760,355) v4(760,310) v4(760,260) v4(760,210) v2(910,60)
  Signal Layer 2 w20: v2(910,60) 920,50 1325,50 TP2.1@1355,80
  Bottom Layer w8: C7.1@980,136.5 987.13,143.62 U2.16@987.13,200.51 ; U2.6@1089.49,287.13 1192.87,287.13 1355,125 TP2.1@1355,80
  Bottom Layer w12: v4(760,210) R11.2@790,210 ; v4(760,260) R12.2@790,260 ; v4(760,310) R13.2@790,310 ; v4(760,355) R10.2@790,355 ; R8.2@890,115 910,115 ; v2(910,60) 910,115 ; C7.1@975,131.5 C7.1@980,136.5 ; C7.1@980,126.5 968.5,115 R9.2@930,115 910,115
5V: C21.1 C26.1 R18.2 TP8.1 U1.4 U1.11 U3.4 U3.11 U4.1 U4.2 | length 3441.6
  Top Layer w10: C26.1@480,507.56 488.68,516.24 U1.11@557.48,516.24 ; C21.1@480,917.56 498.68,936.24 U3.11@557.48,936.24 ; U1.4@742.52,555.62 949.38,555.62 v5(955,550) ; U3.4@742.52,975.62 984.38,975.62 v5(1010,950)
  Top Layer w12: v5(420,480) 447.56,507.56 C26.1@480,507.56
  Top Layer w20: v2(365,918.54) 479.02,918.54 C21.1@480,917.56
  Signal Layer 1 w12: v5(420,480) 424.29,475.7 659.46,475.7 673.76,490 872.43,490 925.43,543 948,543 v5(955,550)
  Signal Layer 2 w10: v5(955,550) 955,643.99 766,832.99 766,857.01 819.99,911 882.01,911 911.01,940 1000,940 v5(1010,950)
  Signal Layer 2 w12: TP8.1@75,820 145,890 336.46,890 v2(365,918.54) 365,945.83 568.74,1149.57 810.43,1149.57 v5(1010,950)
  Bottom Layer w12: R18.2@246.5,440 380,440 v5(420,480)
12Vin: C1.1 C2.1 C3.1 C4.1 C5.1 C6.1 C14.1 C15.1 C18.1 C19.1 C20.1 C24.1 J2.2 TP1.1 U1.7 U2.11 U2.12 U3.7 U4.8 | length 2116
  Signal Layer 2 w25: v2(425,685) 425,659.65 374.36,609.01 374.36,565.95 366.5,558.09 366.5,513.77 372.31,507.96 366.5,502.16 366.5,457.83 374.36,449.97 305,380.59 230,305.59 230,120.53 260.53,90 698.51,90 746.91,138.4 1126.6,138.4 v2(1155,110)
  Bottom Layer w8: U2.12@1050.12,200.51 1050.12,161.38 C6.1@1075,136.5
  Bottom Layer w25: U4.8@235,722.28 235,788.5 C24.1@236.5,790 236.5,816.5 260,840 ; C6.1@1075,126.5 1091.5,110 v2(1155,110)
  Bottom Layer w50: v2(339.49,685) 339.49,668.58 C5.1@365,643.07 ; C18.1@360,1063.07 v2(360,1110) ; C20.1@450,1063.07 v2(450,1110) ; C4.1@455,643.07 475,663.07 485,673.07 v2(485,685)
AVR_RDY: R9.1 TP4.1 U2.17 | length 1199.4
  Top Layer w10: v2(840,60) 869,31 1201.91,31 1314.53,143.62 1661.38,143.62 TP4.1@1725,80
  Bottom Layer w8: v2(840,60) 840,100.06 873.44,133.5 908.5,133.5 R9.1@930,155 953.78,155 971.38,172.6 U2.17@971.38,200.51
AVSN: R15.2 R16.1 U2.3 | length 89.9
  Bottom Layer w8: U2.3@1089.49,334.37 1129.37,334.37 R15.2@1140,345
  Bottom Layer w15: R15.2@1140,345 R16.1@1140,380
AVSP: R14.2 U2.2 | length 94.2
  Bottom Layer w8: U2.2@1089.49,350.12 1103.89,350.12 1115,361.23 1115,390.06 R14.2@1139.94,415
